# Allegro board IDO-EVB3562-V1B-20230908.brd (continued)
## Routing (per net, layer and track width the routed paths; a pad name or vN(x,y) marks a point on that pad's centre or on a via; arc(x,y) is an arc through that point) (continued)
N69867938: length 1.1
  TOP w0.254: R309.1 94.06,25.31 C219.2
N69867940: length 15
  TOP w0.254: v1(96.19,21.11) 96.43,21.35 96.43,24.36 R309.2 ; v1(94.65,21.11) 93.79,21.98 90.56,21.98 89.76,21.18 89.76,19.4 90.2,18.96 U25.10
  BOTTOM w0.254: v1(94.65,21.11) v1(96.19,21.11)
N69867965: length 5.2
  TOP w0.254: U25.8 96.2,20.23 95.61,20.81 95.61,21.57 96.04,22 96.04,23.34 C214.2
N69871260: length 2.1
  TOP w0.127: R454.2 R446.1 104.63,18 104.43,18 104.38,17.95 Q5.1
N69917404: length 3.6
  TOP w0.254: U14.4 17.37,10.84 17.13,10.6 16.46,10.6 C369.1 R138.1 R139.2
N69923813: length 3
  TOP w0.508: C114.2 67.92,71.22 J21.1
N69957333: length 4.4
  TOP w0.127: C147.2 49.18,69.57 J22.1
N69957443: length 26.8
  TOP w0.127: R189.1 53.16,68.64 52.69,68.64 52.43,68.89 52.43,69.52 52.72,69.81 54.51,69.81 55.3,70.6 55.3,72.96 52.66,75.6 50.47,75.6 46.87,79.19 46.87,82.02 50.09,85.24 J22.11
N69960536: length 20.5
  TOP w0.127: R193.1 38.13,69.82 36.35,71.6 36.35,75.24 40.42,79.3 40.42,84.8 J22.13
N69961030: length 3
  TOP w0.508: C163.2 24.98,70.59 24.8,70.77 J23.4
N69961588: length 5.6
  TOP w0.508: J23.5 23.53,70.14 23.85,69.81 C166.2
N69966336: length 22.7
  TOP w0.127: J23.12 18.76,85.83 20.48,84.11 21.39,84.11 31.6,73.9 31.6,72.53 R219.2
N70024964: length 1.2
  TOP w0.127: U29.3 94.02,68.68 R341.1
N70036634: length 1.5
  TOP w0.127: Q6.1 91.98,64.45 91.98,64.61 R456.2
N70058734: length 1.4
  TOP w0.254: R35.1 101.18,70.84 101.31,70.71 U6.3
N70074623: length 3.7
  TOP w0.254: U11.3 9.53,13.58 9.41,13.69 C265.2 8.8,14.01 9.55,14.76 R130.2
N70074833: length 3
  TOP w0.254: R373.2 C266.2 29.14,19.84 29.44,20.14 U12.3
N70075015: length 2.9
  TOP w0.254: R374.2 51.91,13.11 C267.2 51.84,12.56 52.17,12.56 U13.3
N70075198: length 2.5
  TOP w0.254: R375.2 16.1,14.78 C268.2 17.2,14 U14.3
N70088511: length 1.3
  TOP w0.203: R448.1 13.62,34.51 U59.12
N70100637: length 2.1
  TOP w0.127: U7.42 112.69,38.38 112.94,38.13 R414.1
N70130938: length 2.6
  BOTTOM w0.127: C339.2 29.82,57.06 30.9,57.06 31.4,57.56 U17.29
N70140073: length 1.1
  TOP w0.127: Q4.1 9.8,42.71 9.75,42.76 R453.2
N70164941: length 6.6
  TOP w0.254: R787.2 R1061.2 20.42,56.18 R1060.1 20.95,56.78 22.4,56.78 23.42,55.76 U70.9
N70165129: length 2.9
  TOP w0.254: R783.2 R782.2 23.27,54.64 23.51,54.41 U70.12
N70165139: length 7.5
  TOP w0.254: v1(23.62,57.06) 24.01,56.66 U70.7
  TOP w0.508: C810.1 21.05,53.06 v1(21.5,52.61)
  BOTTOM w0.508: v1(23.62,57.06) 21.5,54.94 v1(21.5,52.61)
N70165141: length 1.2
  TOP w0.508: C810.2 20.67,51.85 21.41,51.85
N70165164: length 1.1
  TOP w0.254: C815.2 20.42,54.7 20.35,54.77 R1061.1
N70166760: length 7.8
  TOP w0.254: Q8.1 21.84,41.25 22.28,41.69 C1012.1 R1063.1 22.7,40.55 20.61,40.55 19.97,41.18 R1062.2
N70166762: length 1.3
  TOP w0.254: Q7.3 17.56,42.12 16.98,41.54 R1062.1
N70166881: length 1.1
  TOP w0.254: Q7.1 18.06,44.94 R4.2
N70177512: length 2.8
  TOP w0.254: R1066.1 R1067.2 25.66,12.73 26.26,12.13 U71.4
N70177574: length 2.6
  TOP w0.254: U71.3 26.26,14.32 26.07,14.13 C1014.2 R1065.2
N70177973: length 2.3
  TOP w0.254: R1069.1 R1070.2 32.87,10.45 33.2,10.11 U72.4
N70178035: length 2.7
  TOP w0.254: U72.3 33.63,12.54 32.93,11.84 C1018.2 R1068.2
N70190247: length 5.3
  TOP w0.254: Q10.1 30.07,29.5 R1079.2 30.95,30.4 31.47,30.92 31.8,30.92 33,32.11 R1080.1 C1034.1
N70190249: length 6.1
  TOP w0.254: Q9.3 31.66,29.75 31.85,29.95 R1079.1 32.13,30.39 33.58,31.84 33.58,33.73 R1083.2
N70190329: length 2.8
  TOP w0.127: R1192.1 31.9,26.52 R1078.2
  TOP w0.254: Q9.1 31.16,27.2 31.78,26.57 R1078.2
N70208813: length 6.7
  TOP w0.508: C282.2 88.42,17.62 88.42,22.38 89.15,23.11 89.57,23.11
N70209347: length 2.8
  TOP w0.127: C1035.2 109.76,55.56 109.58,55.74 J10.22
N70209679: length 1.7
  TOP w0.381: C529.1 102.57,15.62 U42.1
N70209681: length 6.9
  TOP w0.381: C529.2 101.34,16.14 101.82,16.62 104.5,16.62 104.87,16.25 104.87,14.61 104.58,14.32 U42.3
N70209685: length 1.8
  TOP w0.254: U42.4 103.17,13.67 102.71,14.13 C527.1
N70209687: length 3.1
  TOP w0.254: U42.5 103.17,13.02 102.79,13.4 102.79,13.4 102.58,13.6 101.6,13.6 101.31,13.89 C527.2
N70209691: length 1.6
  TOP w0.381: C530.1 102.8,15.02 102.85,14.97 U42.2
N70209695: length 1.9
  TOP w0.381: C528.1 102.38,13.06 103.08,12.37 U42.6
N70210897: length 3.6
  TOP w0.254: R1169.2 R1170.1 C1039.1 105.04,23.02 104.35,23.7 U73.5
N70211090: length 2.4
  TOP w0.254: R1171.2 C1045.2 104.78,26.07 104.45,26.4 U73.1
N70266506: length 15.6
  TOP w0.127: R218.2 31.62,74.96 26.19,80.38 26.19,83.78 J23.10
N70266836: length 3.8
  TOP w0.127: v1(35.34,53.88) 34.77,53.32 R1200.1
  BOTTOM w0.127: v1(35.34,53.88) 34.82,54.4 U17.19
N70310222: length 5.8
  TOP w0.508: v1(127.67,16.29) v1(130.84,16.29)
  BOTTOM w0.508: C533.1 126.72,15.34 127,15.62 R461.2 v1(127.67,16.29) ; R462.2 v1(130.84,16.29)
N70310339: length 2.9
  TOP w0.508: U43.5 v1(130.72,11.08)
  BOTTOM w0.508: R460.1 C531.1 130.34,11.14 130.66,11.14 v1(130.72,11.08)
N70379039: length 2
  TOP w0.127: U18.13 121.49,31.04 R1211.2
N76747942: length 2.7
  BOTTOM w0.254: R209.1 32.32,60.77 U17.1
N76750177: length 2.5
  BOTTOM w0.254: U17.2 32.82,61.29 C341.2

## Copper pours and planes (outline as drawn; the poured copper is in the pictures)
GND on TOP (solid shape): 9.88,21 9.88,20.48 8.97,19.56 8.44,19.56 8.44,19.72 8.54,19.72 8.54,20.5 8.44,20.56 8.44,20.73 8.54,20.73 8.54,21.32 9.57,21.32
GND on TOP (solid shape): 40.3,13.26 40.37,13.36 40.48,13.34 41.55,12.26 41.55,11.59 40.93,11.59 40.93,11.49 40.77,11.49 40.77,12.39 40.3,12.39
GND on TOP (solid shape): 34.44,37.39 34.44,34.39 34.37,34.3 34.26,34.32 33.53,35.05 33.53,35.63 32.67,35.63 32.67,37.88 33.43,37.88 33.43,37.98 33.53,37.98 33.53,38.19 33.64,38.19
GND on TOP (solid shape): 94.49,47.23 94.6,47.25 94.66,47.16 94.66,42.79 94.3,42.42 93.72,42.42 93.72,42.21 92.84,42.21 92.74,42.27 92.77,42.38 94.27,43.88 94.27,47.01
GND on TOP (solid shape): 65.5,49.65 65.59,49.62 66.55,48.66 66.55,47.42 66.49,47.33 66.38,47.35 65.28,48.45 65.28,49.44 65.36,49.51 65.43,49.6
GND on TOP (solid shape): 105.95,41.74 105.95,41.16 106.05,41.16 106.05,41 105.96,41 105.95,41.01 105.8,41.08 105.63,41.1 105.33,41.1 105.1,41.23 104.84,41.25 104.76,41.27 104.72,41.35 104.72,41.78 105.91,41.78
GND on TOP (solid shape): 5.3,20.82 5.47,20.75 5.65,20.75 5.73,20.72 5.77,20.64 5.77,20.45 5.4,20.08 5.25,20.08 5.25,20.52 4.42,20.52 4.42,20.06 4.38,19.99 4.3,19.96 4.26,19.97 4.21,19.97 4.21,20.65 4.39,20.82
GND on TOP (solid shape): 86.07,40.65 86.16,40.59 86.14,40.48 85.79,40.13 84.35,40.13 83.67,39.45 83,39.45 82.94,39.54 82.87,39.61 82.83,39.69 82.87,39.77 82.96,39.86 83.03,39.97 83.03,39.98 83.36,40.3 83.73,40.3 84.07,40.65
GND on TOP (solid shape): 94.17,21.13 94.17,21.11 94.35,20.75 94.73,20.64 94.82,20.62 94.85,20.54 94.85,19.53 95.62,18.76 95.63,18.71 95.58,18.68 95.46,18.68 93.12,21.02 93.12,21.65 93.65,21.65
GND on TOP (solid shape): 57.14,51.13 57.14,50.6 57.13,50.56 57.1,50.55 57.05,50.54 56.99,50.53 54.63,50.53 54.63,50.53 54.49,50.55 54.36,50.53 54.3,50.53 54.22,50.46 53.76,50.46 53.66,50.53 53.68,50.64 54.22,51.17 57.1,51.17
GND on TOP (solid shape): 79.73,23.47 79.84,23.49 79.9,23.4 79.9,21.23 79.4,20.72 76.61,20.72 76.45,20.56 76.43,20.56 76.15,20.52 75.94,20.32 75.87,20.27 75.78,20.3 75.36,20.72 75.36,21.64 77,23.29 79.54,23.29
GND on TOP (solid shape): 91.85,8.2 91.94,8.14 91.92,8.03 90.94,7.05 90.71,7.27 86.16,7.27 85.65,6.76 85.61,6.79 85.49,6.86 85.35,6.89 85.34,6.89 84.73,7.5 84.3,7.5 84.14,7.59 83.97,7.62 83.89,7.65 83.86,7.72 83.86,8.2
GND on TOP (solid shape): 35.66,53.45 35.71,53.37 35.71,52.23 34.99,51.51 34.87,51.43 34.79,51.31 34.75,51.28 34.75,51.22 34.73,51.09 34.75,50.95 34.75,50.95 34.75,49.6 34.5,49.6 33.64,50.46 33.64,52.3 33.53,52.4 33.53,53.05 34.88,53.05 35.25,53.41 35.27,53.41 35.42,53.41 35.56,53.46
GND on TOP (solid shape): 19.6,22.46 19.67,22.49 19.74,22.46 19.96,22.33 20.21,22.34 20.3,22.32 20.34,22.24 20.34,19.73 20.32,19.72 19.92,19.72 19.92,19.89 20.1,20.07 20.1,21.14 19.65,21.59 18.98,21.59 18.88,21.65 18.91,21.76
GND on TOP (solid shape): 104.66,8.79 104.75,8.73 104.73,8.62 104.63,8.52 104.63,8.19 103.81,7.37 103.51,7.37 103.43,7.29 103.32,7.27 103.25,7.36 103.25,8.28 103.24,8.28 103.24,8.34 103.25,8.5 103.21,8.65 103.22,8.74 103.3,8.79
GND on TOP (solid shape): 9.77,17.79 9.77,17.64 9.73,17.56 9.64,17.55 9.13,17.42 9.04,16.91 9.03,16.82 8.95,16.77 8.5,16.77 8.48,16.75 8.42,16.78 8.42,18.06 8.45,18.1 9.46,18.1
GND on TOP (solid shape): 87.34,22.85 87.45,22.87 87.51,22.78 87.51,22.64 87.49,22.62 87.49,21.02 87.42,20.95 87.42,20.72 87.05,20.35 83.83,20.35 83.32,20.86 81.45,20.86 81.45,21.6 81.5,21.69 81.59,21.69 81.7,21.66 81.8,21.65 82.54,21.65 82.81,21.72 83,21.92 86.41,21.92
GND on TOP (solid shape): 113.3,34.14 113.41,34.16 113.47,34.07 113.47,32.9 113.82,32.54 113.95,32.54 113.95,31.78 113.9,31.78 113.78,31.67 113.76,31.67 113.76,31.66 112.91,31.66 112.53,32.04 111.18,32.04 111.08,32.1 111.11,32.21 111.34,32.44 111.34,33.74 111.16,33.92 111.14,34.03 111.23,34.09 113.25,34.09
GND on TOP (solid shape): 59.38,19.98 59.32,19.89 59.21,19.91 57.69,21.42 57.69,21.66 58.21,22.17 58.21,22.74 57.62,23.32 57.06,23.32 57.03,23.29 56.92,23.27 56.86,23.37 56.86,23.83 56.27,24.41 55.71,24.41 55.36,24.06 55.05,24.37 55.02,24.48 55.12,24.54 59.38,24.54
GND on TOP (solid shape): 90.48,30.02 90.53,29.93 90.53,26.57 90.47,26.54 90.46,26.55 88.27,26.55 87.92,26.2 87.92,25.92 87.38,25.92 87.37,25.91 87.31,25.93 87.31,26.55 87.21,26.6 87.21,26.78 87.31,26.78 87.31,27.54 87.21,27.54 87.21,27.64 86.81,27.64 86.71,27.7 86.74,27.81 87.01,28.09 88.15,28.09 89.98,29.92 90.01,29.91 90.2,29.92 90.37,30.01
GND on TOP (solid shape): 123.84,9.67 123.93,9.61 123.91,9.5 123.78,9.28 123.78,9.03 123.78,9.02 123.78,8.96 123.76,8.96 123.76,8.41 123.73,8.36 123.67,8.37 123.61,8.44 122.25,8.44 122.24,8.43 122.18,8.45 122.18,8.96 122.16,8.96 122.16,9.11 121.77,9.5 121.75,9.61 121.84,9.67
GND on TOP (solid shape): 23.44,11.31 23.55,11.33 23.62,11.24 24.1,11.24 24.58,10.76 25.98,10.76 26.37,10.36 26.37,9.69 25.68,9.69 25.65,9.65 25.59,9.64 25.56,9.69 24.78,9.69 24.72,9.59 24.54,9.59 24.54,9.69 23.78,9.69 23.78,9.59 23.68,9.59 23.68,9.46 23.55,9.32 23.43,9.29 23.37,9.39 23.37,10.49 23.16,10.49 23.16,10.66 23.37,10.66 23.37,11.24
GND on TOP (solid shape): 46.37,17.23 46.45,17.19 46.67,17.02 46.93,16.99 46.99,16.99 46.99,16.91 48.63,15.27 49.25,15.27 49.44,15.09 49.44,13.21 48.54,12.31 48.43,12.29 48.37,12.38 48.37,13.2 47.35,14.21 47.35,15.54 46.04,16.85 46.01,16.95 46.07,17.02 46.19,17.09 46.29,17.19
GND on TOP (solid shape): 92.16,13.18 92.16,11.86 89.74,11.86 89.43,12.03 89.08,11.95 88.6,12.13 88.23,11.77 88.22,11.73 86,11.73 85.95,11.76 85.96,11.82 86.01,11.87 86.01,12.88 86.37,13.24 89.67,13.24 89.79,13.36 91.98,13.36
GND on TOP (solid shape): 98.22,20.43 98.28,20.52 98.39,20.5 98.55,20.34 102.58,20.34 102.67,20.28 102.65,20.17 102.53,20.05 101.05,20.05 100.7,19.7 100.39,19.7 100.39,18.64 100.62,18.64 100.62,18.32 98.84,18.32 98.39,18.32 98.22,18.49 98.22,19.48 95.84,19.48 95.51,19.8 95.51,20.2 95.57,20.29 95.69,20.27 95.91,20.05 95.91,19.71 98.22,19.71
GND on TOP (solid shape): 94.1,24.98 94.1,24.83 95.49,24.83 95.76,24.56 95.78,24.45 95.68,24.39 95,24.39 95,24.29 94.9,24.29 94.9,23.53 95,23.53 95,23.43 95.49,23.43 95.71,23.21 95.71,22.99 94.1,22.99 94.1,22.84 93.93,22.84 93.93,22.99 92.54,22.99 92.27,23.26 92.25,23.37 92.34,23.43 93.03,23.43 93.03,23.53 93.12,23.53 93.12,24.29 93.03,24.29 93.03,24.39 92.54,24.39 92.27,24.65 92.25,24.76 92.34,24.83 93.93,24.83 93.93,24.98
GND on TOP (solid shape): 18.12,20.98 18.23,21 18.3,20.91 18.3,19.72 13.96,19.72 11.8,17.56 11.69,17.54 11.63,17.63 11.63,18.12 11.66,18.12 11.66,18.7 13.34,20.39 16.75,20.39 17.32,20.21 17.62,20.73 17.64,20.82 17.72,20.85 18,20.85
GND on TOP (solid shape): 29.43,8.65 29.54,8.67 29.6,8.58 29.6,7.39 29.6,7.38 29.7,6.93 30.14,6.78 30.22,6.76 30.26,6.68 30.26,3.16 31.01,2.4 31.04,2.29 30.94,2.23 25.25,2.23 22.97,4.51 22.97,5.85 23.91,5.85 24.06,5.7 25.21,5.7 25.36,5.85 25.89,5.85 28.6,8.55 29.34,8.55
GND on TOP (solid shape): 86.69,39.89 86.77,39.84 86.78,39.75 86.77,39.41 86.98,39.15 87.03,39.07 87.01,38.99 86.79,38.77 85.54,38.77 83.6,36.84 83.26,36.84 83.26,37.13 83.06,37.33 83.05,37.34 82.98,37.49 82.87,37.61 82.83,37.69 82.87,37.77 82.94,37.84 83,37.92 83.25,37.92 84.67,39.34 86.12,39.34 86.66,39.89
GND on TOP (solid shape): 84.23,43.61 85.86,43.61 85.87,43.56 85.93,43.37 86.07,43.23 86.11,43.15 86.08,43.07 85.96,42.92 85.92,42.74 85.88,42.67 85.81,42.64 84.18,42.64 83.57,43.26 83.07,43.26 83.06,43.3 82.99,43.47 82.87,43.61 82.83,43.69 82.87,43.77 82.99,43.9 83.06,44.07 83.07,44.09 83.24,44.26 83.58,44.26
GND on TOP (solid shape): 39.54,50.46 39.63,50.43 40.21,49.85 40.24,49.76 40.19,49.69 40.01,49.52 39.94,49.29 39.94,49.25 38.64,49.25 38.43,49.45 38.4,49.45 38.39,49.48 38.33,49.55 38.27,49.61 38.23,49.69 38.27,49.77 38.34,49.84 38.4,49.92 38.74,49.92 38.93,50.11 38.95,50.11 39.26,50.16 39.47,50.4
GND on TOP (solid shape): 100.86,15.48 101.63,15.48 101.63,14.61 100.83,14.61 100.83,13.65 101.09,13.65 101.47,13.27 101.63,13.27 101.63,12.69 100.88,12.69 100.88,12.15 99.04,12.15 98.39,11.5 98.28,11.48 98.22,11.57 98.22,11.86 95.91,11.86 95.91,11.79 94.61,11.79 94.01,11.19 93.9,11.17 93.84,11.26 93.84,12.8 94.46,13.42 95.91,13.42 95.91,13.36 98.22,13.36 98.22,14.14 98.7,14.14 98.82,14.26 100.14,14.26 100.39,14.51 100.39,15.68 99.96,16.11 99.31,16.11 99.22,16.17 99.24,16.28 99.43,16.48 100.86,16.48
GND on TOP (solid shape): 42.37,17.23 42.45,17.19 42.74,17 43.09,17.03 43.12,17.04 44.94,15.22 44.94,13.01 45.87,12.07 45.87,11.17 45.69,11.13 45.53,11.03 45.5,11.02 45.46,11.03 45.31,11.14 45.12,11.18 45.12,11.93 42.55,14.49 42.55,16.01 41.64,16.93 41.64,17.01 41.7,17.01 41.7,17.01 42.03,17.01 42.29,17.19
GND on TOP (solid shape): 130.02,44.83 130.13,44.86 130.2,44.76 130.2,44.2 130.15,44.2 129.73,43.68 130.23,43.24 130.25,43.24 130.96,42.54 130.96,42.44 130.89,42.44 130.88,42.45 130.51,42.54 130.19,42.34 128.46,42.34 127.58,43.22 127.56,43.33 127.66,43.39 128.58,43.39
GND on TOP (solid shape): 31.3,28.65 31.58,28.65 31.65,28.62 31.68,28.55 32.09,28.07 32.62,28.41 32.84,28.39 33.05,28.48 33.16,28.49 33.21,28.4 33.21,26.2 32.6,26.2 32.26,26.53 32.26,27 31.82,27 31.51,27.31 31.51,28.31 30.93,28.31 30.93,28.36 30.84,28.61 30.63,28.77 30.59,28.79 30.59,29.56 30.94,29.91 31.3,29.91
GND on TOP (solid shape): 31.67,7.55 33.8,7.55 34.18,7.93 34.73,7.93 34.73,7.55 34.95,7.32 35.35,7.32 35.35,5.85 35.87,5.85 35.94,5.77 36.43,5.77 36.51,5.85 38.06,5.85 38.06,7.3 38.35,7.3 38.35,5.85 39.06,5.85 39.06,7.32 39.35,7.32 39.35,5.85 40.44,5.85 40.44,4.24 38.43,2.23 37.02,2.23 36.92,2.29 36.95,2.4 37.53,2.99 37.53,4.2 37.53,4.21 37.07,4.82 36.61,4.21 36.61,4.2 36.61,3.36 36.11,2.87 31.85,2.87 31.17,3.54 31.17,7.77 31.19,7.83 31.19,7.89 31.2,7.94 31.29,7.94
GND on TOP (solid shape): 3.77,18.71 3.96,18.42 4.3,18.34 4.38,18.32 4.42,18.24 4.42,17.91 4.97,17.91 4.98,17.84 4.96,17.76 4.88,17.72 4.42,17.72 4.42,17.11 4.94,17.11 5.03,17.06 5.03,16.96 5.01,16.92 4.42,16.92 4.42,16.9 4.38,16.82 4.3,16.8 4.03,16.77 3.82,16.6 3.62,16.6 3.44,16.42 3.33,16.39 3.27,16.49 3.27,18.52 2.64,18.52 2.64,18.71 3.27,18.71 3.27,18.75 3.76,18.75
GND on TOP (solid shape): 92.12,19.23 92.18,19.32 92.29,19.3 94.75,16.85 95.91,16.85 95.91,16.68 92.12,16.68 92.12,16.94 89.81,16.94 89.81,16.04 89.74,16.04 89.73,16.02 89.13,16.02 88.57,15.46 85.97,15.46 84.36,13.85 84.36,13.21 84.3,13.12 84.19,13.14 84.12,13.21 84.14,13.24 84.16,13.77 83.68,13.99 83.66,13.99 81.14,16.51 81.14,17.05 81.33,17.25 81.4,17.52 81.4,17.62 81.44,17.67 81.49,17.66 82.6,16.54 88.53,16.54 88.63,16.64 88.7,16.64 88.7,16.71 89.67,17.68 89.67,18.9 89.7,18.95 89.76,18.94 89.81,18.88 89.81,18.44 92.12,18.44
GND on TOP (solid shape): 78.31,50.23 78.42,50.25 78.48,50.16 78.48,50.03 77.78,49.33 77.78,48.16 77.61,47.58 78.14,47.29 78.22,47.27 78.26,47.19 78.26,47.14 77.97,46.84 77.94,46.84 77.57,46.74 77.4,46.41 77.33,46.32 77.22,46.34 76.75,46.81 76.76,46.84 76.6,47.26 76.16,47.37 76.07,47.39 76.03,47.47 76.03,47.95
GND on TOP (solid shape): 85.38,3.59 85.48,3.53 85.45,3.41 85.96,2.17 86.47,3.41 86.45,3.53 86.54,3.59 87.18,3.59 88.73,2.04 88.75,1.93 88.65,1.87 85.37,1.87 84.77,2.47 84.77,2.9 84.72,3.18 84.57,3.42 84.56,3.53 84.65,3.59
GND on TOP (solid shape): 94.14,31.53 94.19,31.53 94.19,31.4 94.14,31.4 94.14,30.64 94.15,30.64 94.18,30.58 94.13,30.53 94.11,30.53 94.11,30.51 93.89,30.29 93.89,28.05 94.29,27.64 95.23,27.64 95.32,27.59 95.32,27.49 95.51,26.51 96.51,26.45 96.61,26.45 96.67,26.36 96.67,24.83 96.6,24.74 96.49,24.76 95.96,25.29 95.96,25.78 94.1,25.78 94.1,25.64 93.93,25.64 93.93,25.78 92.31,25.78 92.31,30.03 92.31,30.03 92.31,30.35 92.43,30.87 91.99,31.17 91.97,31.17 91.6,31.55 91.78,31.73 93.09,31.73 93.51,32.15 94.14,32.15
GND on TOP (solid shape): outline of 116 points within 5.9,22.84 16.57,26.45
GND on TOP (solid shape): 88.97,31.96 89.07,31.94 89.99,31.02 90.02,30.92 89.95,30.85 89.68,30.65 89.6,30.32 89.61,30.29 87.93,28.62 86.79,28.62 85.92,27.75 85.92,23.21 85.84,23.12 84.15,23.12 83.07,24.19 83.07,24.21 83.01,24.43 82.87,24.61 82.83,24.69 83.07,25.19 82.83,25.69 82.87,25.77 83.07,26.15 82.92,26.56 82.9,26.67 83,26.73 83.26,26.73 84.87,28.34 84.87,29.49 86.84,31.45 88.28,31.45 88.29,31.45 88.7,31.52 88.9,31.87
GND on TOP (solid shape): 7.64,41.96 7.47,41.76 7.43,41.49 7.44,41.47 7.33,41.36 7.33,41.02 6.22,41.02 6.22,40 3.83,37.61 3.83,34.8 3.13,34.09 2.7,34.09 2.48,34.06 2.27,33.97 2.17,33.97 2.11,34.05 2.11,34.62 2.17,34.71 2.27,34.7 3.43,35.29 2.27,35.88 2.17,35.87 2.11,35.96 2.11,36.56 3.43,36.56 3.43,38.02 2.11,38.02 2.11,41.84 2.66,42.39 5.1,42.39 5.56,42.34 5.84,42.71 5.85,42.75 7.4,42.75 7.4,43.34 7.64,43.34
GND on TOP (solid shape): 17.15,23.07 17.15,22.53 17.14,22.5 17.1,22.48 16.69,21.81 17.46,21.66 17.53,21.69 17.6,21.66 17.7,21.58 17.82,21.54 17.83,21.54 17.88,21.49 17.77,21.39 11.74,21.39 9.43,19.08 9.38,19.07 9.34,19.11 9.34,19.18 10.42,20.26 10.42,21.23 9.79,21.85 6.74,21.85 6.2,21.31 6.1,21.28 6.03,21.35 5.73,21.67 5.3,21.61 4.06,21.61 3.42,20.97 3.42,20.36 3.18,20.12 2.85,20.12 2.64,20.12 2.64,22.3 3.36,23.02 6.13,23.02 7.07,22.08 11.64,22.08 15.12,22.81 15.68,22.81 15.68,22.77 16.35,22.35 16.51,23.12 16.48,23.2 16.51,23.27 16.58,23.37 16.63,23.48 16.63,23.5 16.68,23.54
GND on TOP (solid shape): 78.37,17.23 78.87,16.98 79.37,17.23 79.87,16.98 80.37,17.23 80.45,17.19 80.52,17.11 80.6,17.05 80.6,16.29 81.57,15.32 81.6,15.21 81.5,15.15 79.68,15.15 79.15,14.62 79.15,13.52 79.43,13.24 80.7,13.24 80.93,13.01 80.93,11.81 80.95,11.79 80.93,11.73 76.22,11.73 76.07,11.88 76.07,11.9 75.83,12.39 75.28,12.33 75.22,12.31 75.15,12.33 75.14,12.34 75.11,12.42 75.14,12.49 75.3,12.74 75.28,13.03 75.3,13.12 75.38,13.16 77.18,13.16 78.07,14.05 78.07,15.61 77.83,15.84 77.83,16.53 77.84,16.54 77.85,16.69 77.82,16.85 77.83,16.94 77.91,16.98 78.12,17.05 78.29,17.19
GND on TOP (solid shape): 118.41,11.58 118.44,11.48 118.37,11.41 118.14,11.24 118.05,10.97 118.03,10.94 118,10.92 117.94,10.92 117.9,10.93 117.88,10.95 117.53,11.27 117.08,11.14 117,11.1 116.93,11.14 116.27,11.2 116.18,10.55 116.2,10.48 116.17,10.42 116.14,10.39 116.11,10.36 116.08,10.34 116.05,10.34 115.41,10.17 115.55,9.53 115.55,8.99 115.42,8.99 115.42,7.08 115.55,7.08 115.55,5.73 115.62,5.66 115.64,5.53 115.52,5.49 115.25,5.53 114.98,5.5 114.89,5.52 114.85,5.6 114.85,7.11 114.94,7.11 114.94,7.69 115.19,7.94 115.19,9.66 115.19,9.67 115.19,9.69 115.14,9.99 114.92,10.19 114.9,10.22 114.9,10.26 114.92,10.58 114.73,10.84 114.73,11.49 115.9,11.49 115.9,11.89 116.09,12.09 117.91,12.09
GND on TOP (solid shape): outline of 108 points within 74.59,4.33 82.97,10.94
GND on BOTTOM (solid shape): 56.19,55.51 52.59,55.51 52.59,59.11 56.19,59.11
GND on BOTTOM (solid shape): 61.37,49.36 61.05,49.03 60.94,49.01 60.88,49.11 60.88,51.98 61.37,51.98
GND on BOTTOM (solid shape): 56.15,50.6 56.4,50.35 56.4,49.83 56.32,49.75 55.79,49.75 55.79,50.45 55.69,50.45 55.69,50.55 55.48,50.55 55.48,50.76 55.29,50.94 55.29,51.17 55.5,51.17 55.5,51.98 56.15,51.98
GND on BOTTOM (solid shape): 74.48,51.16 74.48,49.97 74.09,49.57 73.69,49.57 73.69,51.32 73.64,51.37 73.63,51.43 73.67,51.46 73.77,51.46 73.98,51.67
GND on BOTTOM (solid shape): 77.28,52.27 76.63,51.62 76.52,51.6 76.46,51.7 76.46,51.89 76.25,51.89 76.25,52.04 76.73,52.53 76.73,53.31 76.8,53.37 77.28,53.37
GND on BOTTOM (solid shape): 113.47,58.62 113.47,56.68 113.39,56.61 113.32,56.52 113.25,56.47 113.16,56.49 112.82,56.83 112.82,58.71 113.39,58.71
GND on BOTTOM (solid shape): 69.28,56.14 69.37,56.14 69.37,56.04 70.21,56.04 70.21,55.73 70,55.52 68.79,55.52 68.12,54.84 65.7,54.84 65.63,54.92 65.62,54.97 65.66,55 66.99,55 66.99,56.28 67.37,56.66 69.28,56.66
GND on BOTTOM (solid shape): 20.27,46.53 20.34,46.62 20.45,46.6 22.44,44.61 22.46,44.5 22.37,44.44 22.03,44.44 20.27,46.2
GND on BOTTOM (solid shape): 71.12,5.32 71.22,5.25 71.19,5.14 70.84,4.79 67.95,4.79 67.86,4.85 67.88,4.96 68.24,5.32
GND on BOTTOM (solid shape): 85.64,19.87 85.66,19.76 85.57,19.69 85.09,19.69 82.95,21.84 82.93,21.95 83.02,22.01 83.5,22.01
GND on BOTTOM (solid shape): 101.11,12.22 101.14,12.11 101.04,12.04 98.7,12.04 98.34,12.4 98.32,12.51 98.41,12.57 100.76,12.57
GND on BOTTOM (solid shape): 112.41,35.96 112.51,35.9 112.48,35.79 112.11,35.42 107.72,35.42 107.63,35.48 107.65,35.59 108.02,35.96
GND on BOTTOM (solid shape): 58.9,21.39 59,21.33 58.97,21.22 56.85,19.09 43.05,19.09 42.95,19.15 42.97,19.26 43.2,19.49 43.2,21.39
GND on BOTTOM (solid shape): 83.8,10.03 83.86,10.12 83.98,10.1 86.1,7.97 86.12,7.86 86.03,7.8 84.94,7.8 84.75,7.6 83.8,8.55
GND on BOTTOM (solid shape): 31.58,25.65 31.86,25.37 31.87,25.31 31.83,25.28 31.8,25.28 31.12,24.6 30.68,24.6 30.59,24.66 30.61,24.77 31.46,25.63 31.46,26.82 31.58,26.82
GND on BOTTOM (solid shape): 49.08,56.77 49.18,56.77 49.18,56.67 49.94,56.67 49.94,56.69 50.01,56.72 50.44,56.29 50.44,56 50.16,55.72 50.06,55.69 49.99,55.76 48.13,55.76 48.13,55.54 47.78,55.54 47.56,55.76 47.31,55.76 47.31,57.04 47.56,57.3 49.08,57.3
GND on BOTTOM (solid shape): 111.26,15.44 111.26,15.3 113.14,13.42 113.16,13.31 113.07,13.25 112.11,13.25 110.18,15.17 110.16,15.28 110.26,15.34 110.77,15.34 110.98,15.56 111.15,15.56
GND on BOTTOM (solid shape): 115.6,17.5 115.6,16.92 115.69,16.92 115.69,16.85 115.67,16.84 115.56,16.65 115.54,16.43 115.54,16.41 115.46,16.33 115.1,16.33 113.72,17.71 111.86,17.71 111.78,17.8 111.77,17.85 111.82,17.88 115.23,17.88
GND on BOTTOM (solid shape): 117.75,11.42 117.75,11.34 117.7,11.26 117.61,11.25 117.49,11.28 117.36,11.28 117.33,11.28 117.03,11.59 117.03,11.94 116.47,12.5 116.46,12.55 116.51,12.58 116.59,12.58
GND on BOTTOM (solid shape): 54.55,51.17 54.76,51.17 54.76,50.72 54.78,50.63 54.73,50.56 54.73,50.52 54.67,50.52 54.66,50.52 54.51,50.55 54.36,50.53 54.35,50.53 54.3,50.53 54.3,50.72 53.81,50.72 53.81,51.98 54.39,51.98 54.39,52.07 54.55,52.07
GND on BOTTOM (solid shape): 117.38,45.65 117.38,40.95 117.48,40.85 117.51,40.74 117.41,40.67 110.12,40.67 107.25,43.55 107.22,43.66 107.32,43.72 107.83,43.72 109.25,45.14 109.25,46.66 109.61,47.02 116.01,47.02
GND on BOTTOM (solid shape): 37.03,55.5 37.06,55.55 37.11,55.54 37.9,54.76 38.22,54.76 38.22,54.55 39.12,54.55 39.12,54.39 39.02,54.39 39.02,53.63 39.12,53.63 39.12,53.53 39.33,53.53 39.33,52.42 38.32,51.4 38.21,51.38 38.15,51.48 38.15,54.26 37.03,55.38
GND on BOTTOM (solid shape): 49.55,60.08 49.66,60.1 49.73,60.01 49.73,59.57 50.36,58.93 50.36,58.62 50.54,58.44 50.58,58.38 50.58,58.32 50.54,58.3 50.04,58.3 50.04,58.86 49.94,58.86 49.94,58.96 49.36,58.96 49.11,59.22 49.11,59.87 49.34,59.87
GND on BOTTOM (solid shape): 88.62,27.83 88.65,27.75 88.61,27.68 88.5,27.61 88.26,27.61 88.16,27.83 88.18,27.98 84.5,31.66 84.47,31.77 84.57,31.83 84.62,31.83
GND on BOTTOM (solid shape): 31.71,32.44 31.73,32.33 31.64,32.27 31.41,32.27 29.92,30.78 29.81,30.76 29.75,30.85 29.75,31.25 29.35,31.66 27.44,31.66 27.41,31.69 27.33,31.69 27.24,31.78 27.22,31.82 27.23,31.85 27.33,32.03 27.35,32.23 27.34,32.26 27.8,32.71 31.44,32.71
GND on BOTTOM (solid shape): 6.64,49.56 6.74,49.56 6.74,49.47 6.95,49.47 6.95,49.35 6.79,49.35 6.79,47.49 7.01,47.49 7.1,47.43 7.08,47.32 6.89,47.13 6.89,45.79 5.7,45.79 5.54,45.95 5.52,46.02 5.52,46.18 5.6,46.29 5.62,46.43 5.62,47.38 5.11,47.89 5.11,48.42 5.75,48.42 5.75,48.44 5.82,48.52 5.85,48.52 5.85,48.54 6,48.7 6,50.41 6.64,50.41
GND on BOTTOM (solid shape): 32.98,8.63 33.16,8.81 33.4,8.71 33.47,8.59 33.84,8.59 33.86,8.57 34.34,8.57 34.93,7.98 34.95,7.87 34.85,7.81 32.33,7.81 32.23,7.71 31.41,7.71 31.32,7.77 31.34,7.88 31.57,8.11 32.55,8.11 32.97,8.53
GND on BOTTOM (solid shape): 125.88,25.45 126.26,25.07 126.26,24.4 126.16,24.3 125.57,24.3 125.48,24.37 125.5,24.48 125.73,24.71 125.73,25.84 125.31,26.26 125.31,30.3 125.55,30.53 125.55,31.14 125.22,31.47 125.25,31.5 125.34,31.87 125.14,32.18 125.1,32.26 125.13,32.34 125.46,32.67 125.88,32.67
GND on BOTTOM (solid shape): 118.08,20.04 118.19,20.07 118.26,19.97 118.26,17.03 117.97,16.74 117.88,16.71 117.8,16.77 117.6,16.97 117.31,17.02 117.29,17.01 116.73,17.57 116.66,17.57 116.66,17.78 116.08,17.78 115.9,17.96 115.88,18.07 115.97,18.14 116.18,18.14
GND on BOTTOM (solid shape): 122.73,10.96 122.77,10.89 122.77,10.08 123.55,9.29 122.56,8.3 120.81,8.3 120.72,8.36 120.74,8.47 121.22,8.95 121.23,8.95 121.64,9.26 121.54,9.76 121.52,9.78 121.52,9.93 122.58,10.98 122.65,10.99
GND on BOTTOM (solid shape): 112.32,16.04 112.72,15.69 113.2,15.92 113.27,15.97 113.35,15.94 113.65,15.64 113.65,15.2 114.67,14.18 114.69,14.07 114.6,14.01 113.69,14.01 112.05,15.65 112.05,15.77 111.91,15.91 111.89,16.02 111.98,16.08 112.31,16.08
GND on BOTTOM (solid shape): 34.73,51.3 34.75,51.3 34.75,51.23 34.75,51.22 35.21,50.61 35.67,51.22 35.67,51.23 35.67,51.3 36.17,51.3 36.17,50.22 36.11,50.12 36,50.15 35.78,50.36 34.13,50.36 33.83,50.67 33.83,52.1 34.58,52.1 34.58,52.2 34.73,52.2
GND on BOTTOM (solid shape): 23.19,22.64 23.53,22.64 23.62,22.58 23.6,22.47 23.19,22.05 22.81,22.05 22.73,22.1 22.72,22.2 22.55,22.78 21.95,22.73 21.88,22.7 21.81,22.73 21.79,22.75 21.79,22.82 21.85,22.82 22.31,23.27 22.56,23.27
GND on BOTTOM (solid shape): 30.71,55.28 30.82,55.3 30.88,55.21 30.88,54.98 31.16,54.69 31.38,54.69 31.41,54.65 31.44,54.62 31.31,54.24 31.52,53.89 31.52,53.48 31.26,53.23 31.26,53.16 31.05,53.16 31.05,51.66 30.99,51.56 30.88,51.59 29.84,52.62 29.23,52.62 29.02,52.83 29.02,52.99 29.12,52.99 29.12,53.75 29.02,53.75 29.02,53.91 29.92,53.91 29.92,54.49
GND on BOTTOM (solid shape): 47.56,55.01 48.13,55.01 48.13,54.8 49.03,54.8 49.03,54.64 48.93,54.64 48.93,53.88 49.03,53.88 49.03,53.78 49.47,53.78 49.51,53.75 49.5,53.7 49.44,53.63 49.44,52.87 48.67,52.87 48.67,52.94 48.47,53.14 47.63,53.14 47.54,53.05 47.44,53.05 47.44,52.95 47.38,52.89 47.38,52.54 47.37,52.5 47.31,52.4 47.21,52.34 47.14,52.32 46.92,52.1 46.03,52.1 45.92,52.1 45.87,52.19 45.87,53.53 46.16,53.53 46.16,53.63 46.26,53.63 46.26,54.39 46.16,54.39 46.16,54.64 46.26,54.64 46.26,55.22 46.27,55.23 47.34,55.23
GND on BOTTOM (solid shape): 85.17,11.6 85.2,11.65 85.26,11.64 87.48,9.42 90.77,9.42 91.21,9.86 96.5,9.86 96.79,9.57 96.81,9.47 96.73,9.4 96.49,9.3 96.34,9.09 96.33,9.05 96.29,9.05 96.21,9.09 96.19,9.17 95.9,9.69 95.32,9.53 93.79,9.53 93.47,9.53 93.01,9.07 87.61,9.07 85.17,11.51
GND on BOTTOM (solid shape): 60.98,18.84 61.09,18.55 61.36,18.39 61.37,18.39 63.44,16.33 63.44,16.31 63.46,16.17 63.52,16.04 63.53,15.94 63.44,15.88 59.46,15.88 59.37,15.93 59.36,16.02 59.26,16.51 58.78,16.64 58.77,16.63 58.1,16.63 57.46,15.99 57.38,15.99 57.33,16.02 57.34,16.08 60.16,18.89 60.98,18.89
GND on BOTTOM (solid shape): 21,22.82 21.09,22.76 21.08,22.66 21.04,22.18 21.45,21.91 21.48,21.89 21.5,21.86 21.5,21.79 21.8,21.49 21.82,21.38 21.73,21.32 20.5,21.32 19.76,22.07 19.76,22.26 19.8,22.35 19.9,22.36 20.34,22.39 20.56,22.77 20.56,22.82
GND on BOTTOM (solid shape): 129.62,43.52 129.71,43.55 129.79,43.5 130.07,43.26 130.44,43.3 130.54,43.3 130.59,43.21 130.59,42.55 130.54,42.55 130.34,42.48 130.19,42.34 129.84,42.34 128.44,40.93 128.34,40.91 128.27,40.99 128.11,41.29 127.78,41.41 127.71,41.43 127.68,41.51 127.68,41.58
GND on BOTTOM (solid shape): 9.18,43.13 9.24,43.22 9.35,43.2 9.47,43.08 9.47,40.17 9.41,40.08 9.3,40.1 8.93,40.46 8.97,40.5 9.03,41.07 8.49,41.29 8.39,41.31 8.36,41.41 8.36,41.71 8.19,41.95 8.14,42.02 8.17,42.1 9.18,43.11
GND on BOTTOM (solid shape): 84.77,6.15 84.85,6.18 84.92,6.14 84.97,6.08 85.03,6.02 85.08,5.95 85.05,5.87 84.02,4.84 74.09,4.84 74.04,4.94 73.97,5.03 73.95,5.14 74.04,5.2 75.27,5.2 75.73,5.66 76.29,5.66 76.36,5.63 76.39,5.55 76.58,5.17 77,5.09 77.01,5.09 79.05,5.09 79.05,5.09 79.48,5.17 79.67,5.55 79.7,5.63 79.77,5.66 83.16,5.66 83.31,5.81 84.42,5.81
GND on BOTTOM (solid shape): 63.32,60.44 63.37,60.37 63.46,60.14 63.66,59.99 63.72,59.91 63.7,59.82 62.02,58.15 61.97,58.15 61.96,58.16 61.87,58.23 61.76,58.28 61.73,58.29 61.73,58.84 61.76,58.92 61.85,58.94 62.37,59.19 62.28,59.76 62.24,59.8 62.32,59.88 62.35,59.86 62.81,59.9 63.02,60.31 63.05,60.38 63.11,60.42 63.17,60.43 63.23,60.45
GND on BOTTOM (solid shape): 65.41,19.2 65.4,19.19 65.39,18.84 65.61,18.58 65.62,18.57 68.13,16.06 68.16,15.95 68.06,15.88 64.39,15.88 64.3,15.94 64.31,16.04 64.38,16.42 64.15,16.73 64.14,16.74 62.33,18.54 62.31,18.64 62.37,18.71 62.47,18.77 62.55,18.84 62.64,18.88 62.72,18.83 63.04,18.61 63.42,18.71 63.46,18.72 63.49,18.7 63.83,18.51 64.19,18.63 64.77,18.53 65.01,19.06 65.17,19.13 65.29,19.24 65.3,19.26 65.41,19.26
GND on BOTTOM (solid shape): 69.79,27.33 69.86,27.33 69.91,27.3 69.9,27.25 69.77,27.12 69.75,27.12 69.3,26.95 69.24,26.47 69.23,26.38 69.14,26.33 68.86,26.33 68.85,26.32 68.82,26.32 68.28,25.8 68.92,25.4 68.96,25.4 68.99,25.38 69.03,25.3 68.96,25.24 68.93,25.24 68.4,24.87 68.73,24.31 68.8,24.24 68.78,24.14 68.67,23.92 68.69,23.68 68.67,23.58 68.59,23.54 65.92,23.54 65.44,24.02 65.45,24.04 65.39,24.34 65.17,24.55 65.12,24.62 65.14,24.71 67.91,27.48 69.64,27.48
GND on BOTTOM (solid shape): 93.14,33.98 93.25,34.01 93.32,33.91 93.32,32.46 93.12,32.27 93.12,31.72 93.16,31.66 93.19,31.55 93.16,31.44 93.12,31.37 93.12,31.04 93.16,30.98 93.19,30.87 93.16,30.76 93.12,30.69 93.12,30.41 93.32,30.22 93.32,29.03 93,28.71 93,28.69 92.93,28.66 92.31,29.28 92.31,30.35 92,31.17 91.64,30.36 91.65,30.35 91.65,30.22 91.59,30.22 91.51,30.23 91.43,30.24 91.34,30.27 91.32,30.37 91.06,30.94 90.46,30.76 90.43,30.74 90.39,30.75 90.34,30.78 90.34,30.95 92.27,32.88 92.29,32.88 92.78,33.11 92.73,33.65 92.72,33.76 92.81,33.81 92.98,33.81
GND on BOTTOM (solid shape): 70.48,18.36 75.82,18.36 76.75,19.29 76.86,19.31 76.92,19.21 76.92,16.81 76.92,16.8 77.1,16.28 77.65,16.28 79.59,16.28 79.77,16.1 79.79,15.99 79.7,15.93 77.16,15.93 76,14.76 76.11,14.66 76.11,14.49 76.05,14.4 75.94,14.42 74.59,15.76 74.59,16.31 74.74,16.45 74.77,16.45 75.28,17.1 74.47,17.23 74.39,17.19 74.31,17.23 73.59,17.24 73.68,16.53 73.68,15.91 73.62,15.81 73.51,15.84 71.9,17.44 69.87,17.44 68.07,19.24 68.07,19.27 67.94,19.68 67.53,19.81 67.5,19.81 67.12,20.19 66.42,20.19 65.93,20.67 65.91,20.79 66,20.85 67.99,20.85
GND on BOTTOM (solid shape): 16.07,44.04 16.1,43.96 16.05,43.88 15.81,43.48 16.02,43.07 16.02,42.7 16.79,41.93 17.58,41.93 19.72,39.79 19.73,39.67 19.61,39.62 16.39,38.11 17.64,34.77 17.7,34.66 17.6,34.58 16.69,34.58 16.14,34.02 16.14,33.1 17.68,31.55 21.37,31.55 21.76,31.16 21.78,31.05 21.68,30.99 17.78,30.99 16.97,30.19 16.95,30.19 16.85,30.19 16.75,30.18 16.67,30.19 16.63,30.25 16.17,30.61 15.7,30.26 15.66,30.21 15.59,30.19 15.37,30.17 15.19,30.06 14.4,29.87 14.92,29.24 14.94,29.25 15.26,28.93 15.28,28.82 15.19,28.76 13.19,28.76 12.11,29.84 12.08,29.92 12.12,30 12.28,30.2 12.32,30.45 12.31,30.48 13.3,31.46 13.3,37.54 10.76,40.07 10.76,44.03 10.54,44.26 10.54,44.31 10.59,44.36 10.72,44.23 15,44.23 15.44,44.67
GND on BOTTOM: 75.85,63.53 75.8,63.58 75.8,64.35 75.66,64.49 75.66,65.96 75.65,65.96 75.65,66.78 76.07,67.2 76.65,67.2 76.82,67.04 76.82,66.78 76.39,66.35 76.39,66.1 76.31,66.03 76.31,64.44 76.39,64.36 76.39,63.58 76.33,63.53
GND on L2-VCC: 0.51,87.97 0.95,89.05 2.03,89.49 118.47,89.49 118.65,89.31 118.65,88.55 118.78,88.42 122.97,88.42 123.1,88.55 123.1,89.31 123.27,89.49 132.97,89.49 134.05,89.05 134.49,87.97 134.49,2.03 134.05,0.95 132.97,0.51 2.03,0.51 0.95,0.95 0.51,2.03 ; 5 cut-outs
GND on L3-GND: 2.03,0.51 0.95,0.95 0.51,2.03 0.51,87.97 0.95,89.05 2.03,89.49 13.75,89.49 13.75,77.29 15.32,75.72 17.69,75.72 18.7,76.74 18.7,78.77 16.92,80.55 16.92,86.56 17.13,86.77 31.32,86.77 31.53,86.56 31.53,80.8 29.75,79.03 29.75,76.87 31.02,75.6 36.31,75.6 37.75,77.04 37.75,78.6 35.85,80.51 35.85,85.93 36.69,86.77 50.62,86.77 50.96,86.44 50.96,81.02 49.05,79.11 49.05,76.78 50.24,75.6 56.12,75.6 57.69,77.17 57.69,78.73 55.53,80.89 55.53,86.18 55.87,86.52 70.18,86.52 70.39,86.31 70.39,80.76 68.49,78.86 68.49,76.91 69.67,75.72 72.13,75.72 73.44,77.04 73.44,89.49 118.47,89.49 118.65,89.31 118.65,88.55 118.78,88.42 122.97,88.42 123.1,88.55 123.1,89.31 123.27,89.49 132.97,89.49 134.05,89.05 134.49,87.97 134.49,2.03 134.05,0.95 132.97,0.51
GND_EARTH on TOP: 32.54,87.03 31.78,87.79 16.67,87.79 15.91,87.03 15.91,80.04 17.69,78.26 17.69,77.2 17.23,76.75 15.77,76.75 14.76,77.76 14.76,89.49 72.42,89.49 72.42,77.5 71.66,76.74 70.14,76.74 69.5,77.38 69.5,78.52 71.41,80.42 71.41,86.77 70.64,87.54 55.4,87.54 54.52,86.65 54.52,80.42 56.67,78.26 56.67,77.63 55.66,76.61 50.71,76.61 50.07,77.25 50.07,78.65 51.98,80.55 51.98,86.9 51.09,87.79 36.23,87.79 34.83,86.39 34.83,80.17 36.74,78.26 36.74,77.5 35.85,76.61 31.5,76.61 30.77,77.35 30.77,78.57 32.54,80.35
GND_EARTH on BOTTOM: 2.95,78.77 13.57,78.77 14.76,79.97 14.76,89.49 72.42,89.49 72.42,77.5 71.51,76.59 70.29,76.59 69.5,77.38 69.5,78.52 71.41,80.42 71.41,86.77 70.64,87.54 55.4,87.54 54.52,86.65 54.52,80.42 56.67,78.26 56.67,77.63 55.66,76.61 50.71,76.61 50.07,77.25 50.07,78.65 51.98,80.55 51.98,86.9 51.26,87.61 36.05,87.61 34.83,86.39 34.83,80.75 36.94,78.65 36.94,77.3 36.15,76.51 31.35,76.51 30.61,77.25 30.61,78.42 32.54,80.35 32.54,87.03 31.96,87.61 16.49,87.61 15.91,87.03 15.91,80.09 17.69,78.32 17.69,77.2 17.25,76.77 9.84,76.77 9.18,76.11 9.18,73.52 7.08,71.41 3.24,71.41 1.75,72.91 1.75,77.57
GND_EARTH on L2-VCC: 72.45,77.48 71.69,76.72 70.29,76.72 69.53,77.48 69.53,78.49 71.43,80.4 71.43,86.75 70.67,87.51 55.43,87.51 54.54,86.62 54.54,80.4 56.57,78.37 56.57,77.48 55.68,76.59 50.73,76.59 50.1,77.22 50.1,78.62 52,80.53 52,86.88 51.11,87.76 36.25,87.76 34.86,86.37 34.86,80.35 36.96,78.24 36.96,77.25 36.3,76.59 31.5,76.59 30.77,77.33 30.77,78.57 32.57,80.37 32.57,87 31.81,87.76 16.7,87.76 15.93,87 15.93,80.07 17.69,78.32 17.69,77.2 17.2,76.72 15.81,76.72 14.79,77.73 14.79,89.47 72.45,89.47
GND_EARTH on L3-GND: 32.54,86.98 31.74,87.79 16.71,87.79 15.91,86.98 15.91,80.04 17.69,78.26 17.69,77.25 17.18,76.74 15.74,76.74 14.76,77.71 14.76,89.49 72.42,89.49 72.42,77.46 71.7,76.74 70.09,76.74 69.5,77.33 69.5,78.44 71.41,80.34 71.41,86.73 70.6,87.54 55.45,87.54 54.52,86.6 54.52,80.47 56.67,78.31 56.67,77.59 55.7,76.61 50.66,76.61 50.07,77.21 50.07,78.69 51.98,80.59 51.98,86.86 51.04,87.79 36.27,87.79 34.83,86.35 34.83,80.09 36.74,78.18 36.74,77.46 35.89,76.61 31.53,76.61 30.77,77.38 30.77,78.52 32.54,80.3
VBAT_WL_1T1R on TOP: 126.25,25.48 125.92,25.81 125.13,25.81 124.95,25.64 124.39,25.64 124.39,25.65 122.98,25.65 122.97,25.66 122.97,26.42 123.07,26.53 126.12,26.53 126.25,26.65 127.5,26.65 127.5,25.5 127.44,25.43 127.31,25.43 127.31,24.29 127.21,24.19 126.45,24.19 126.25,24.39
VCC1V2_DVP on BOTTOM: 16.67,8.21 13.55,11.34 13.55,12.52 10.14,15.92 10.14,17.81 9.68,18.27 8.24,18.27 7.07,19.44 7.07,19.77 7.27,19.97 8.16,19.97 8.17,19.96 8.33,19.96 9,19.29 10.4,19.29 11.22,18.46 11.22,17.06 14.76,13.52 14.76,12.68 14.73,12.48 14.76,12.3 14.76,12.29 14.76,11.84 17.05,9.56 20.07,9.56 20.33,9.3 20.33,8.52 20.02,8.21
VCC1V8_DVP on TOP: 31.02,16.16 31.02,17.18 31.02,18.52 31.12,18.63 31.88,18.63 32.09,18.42 32.09,17.97 32.32,17.74 33.31,17.74 33.51,17.53 33.51,16.11 33.18,15.78 31.4,15.78
VCC1V8_DVP on BOTTOM: 5.87,19.06 5.87,20.43 6.43,20.99 7.09,20.99 7.42,20.66 7.42,20.43 6.89,19.9 6.89,19.31 8.24,17.97 8.85,17.97 9.93,16.89 9.93,15.72 12.63,13.01 12.63,11.89 16.49,8.03 22.77,8.03 23.02,7.78 23.02,7.37 22.82,7.17 15.7,7.17 11.67,11.21 11.67,12.35 8.77,15.25 8.77,16.16
VCC2V8_DVP on TOP: 12.28,11.49 11.67,11.49 11.59,11.41 11.59,8.54 11.82,8.31 13.42,8.31 13.6,8.49 13.6,10.37 13.49,10.47 12.66,10.47 12.4,10.73 12.4,11.36
VCC2V8_DVP1 on TOP: 24.06,6.05 24.06,7.22 24.75,7.91 25.53,7.91 25.61,7.98 25.62,7.98 25.79,8.09 25.9,8.26 25.9,8.27 25.94,8.31 25.94,8.67 25.76,8.85 25.76,9.41 25.79,9.43 27.64,9.43 27.85,9.63 27.85,12.43 27.92,12.5 28.56,12.5 28.68,12.38 28.68,11.01 28.96,10.73 29.85,10.73 29.98,10.6 29.98,9.56 29.23,8.81 28.49,8.81 25.79,6.1 25.26,6.1 25.1,5.95 24.16,5.95
VCC2V8_DVP2 on TOP: 36.08,10.68 35.26,10.68 35.21,10.62 35.21,9.43 34.98,9.2 34.98,7.65 35.06,7.58 36,7.58 36.02,7.55 36.02,6.05 36.05,6.03 36.33,6.03 36.35,6.05 36.35,7.65 37.35,8.64 37.35,9.51 37.19,9.66 36.3,9.66 36.11,9.85 36.11,10.64
VCC3V3_E on TOP: 101.23,27.85 101.1,27.72 97.31,27.72 97.19,27.85 97.19,28.96 97.26,29.04 97.59,29.04 97.77,29.22 97.77,29.8 98.28,30.31 99.88,30.31 99.98,30.41 103.59,30.41 103.82,30.18 103.82,29.42 103.72,29.32 103.67,29.32 103.67,29.34 101.63,29.34 101.23,28.94
VCC3V3_PHY0 on BOTTOM: 56.49,59.01 56.49,59.39 57.01,59.9 57.18,59.9 58.15,60.87 59.72,60.87 59.82,60.97 59.82,61.09 59.95,61.22 61.02,61.22 61.07,61.17 61.07,61.02 61.22,60.87 61.66,60.87 61.75,60.86 62.01,60.87 62.09,60.79 62.09,60.43 62.08,60.43 62.05,60.25 62.08,60.07 62.09,60.06 62.09,60 62.01,59.93 60.79,59.93 60.71,59.85 60.71,59.32 60.54,59.14 59.85,59.14 59.72,59.27 59.72,59.9 59.67,59.95 58.86,59.95 58.81,59.99 58.76,60.02 58.36,60.04 58.08,59.74 58.08,59.73 57.36,59.01 56.74,59.01
VCC3V3_PHY2 on BOTTOM: 77.53,58.83 77.45,58.92 77.44,58.92 76.63,58.92 76.56,58.99 76.56,59.29 77.88,60.61 77.88,61.96 78.7,62.77 79.15,62.77 79.4,62.52 79.4,62.39 79.4,62.35 79.41,62.3 79.41,61.88 79.61,61.68 79.61,60.61 79.56,60.56 79.43,60.56 78.39,59.52 78.39,58.88 78.34,58.83
VCC3V3_SD_OUT on TOP: 109.62,69.39 109.38,69.63 109.38,70.48 109.4,70.48 109.4,71.69 109.38,71.69 109.38,71.79 109.35,71.81 108.34,71.81 107.86,72.3 107.12,72.3 106.94,72.47 106.94,73.64 106.66,73.92 106.66,74.62 106.67,74.67 106.67,74.73 106.67,76.33 106.67,76.38 106.66,76.51 106.99,76.84 107.5,76.84 107.73,76.61 107.73,74.45 108.49,73.69 109.68,73.69 109.72,73.65 109.76,73.65 110.6,72.82 110.6,72.42 110.59,72.42 110.59,71.17 110.51,70.94 110.56,70.69 110.6,70.62 110.6,70.59 110.78,70.42 110.78,69.5 110.66,69.39
VCC3V3_SD_OUT on TOP: 101.12,55.35 100.9,55.58 100.9,56.19 101.01,56.31 102.28,56.31 102.47,56.12 102.47,55.7 102.3,55.52 102.3,55.46 102.19,55.35
VCC3V3_SD_OUT on TOP: 91.47,31.78 91.36,31.78 89.31,33.83 89.31,34.07 89.69,34.45 90.2,34.45 91.98,32.67 91.98,32.29
VCC3V3_SD_OUT on BOTTOM: 102.27,31.4 102.16,31.45 102.04,31.47 102.02,31.47 101.84,31.66 101.84,32.39 102.06,32.62 102.6,32.62 103.79,33.81 103.79,34.96 103.28,35.47 103.28,42.7 102.9,43.09 102.9,49.41 103.23,49.74 103.87,49.74 104.02,49.59 104.02,49.56 104.05,49.56 104.17,49.44 104.17,43.85 104.55,43.47 104.55,36.48 105.27,35.77 105.27,33.08 103.59,31.4
VCC3V3_SD_OUT on BOTTOM: 88.22,31.66 87.41,32.46 87.41,33.05 88.55,34.2 90.46,34.2 91.09,33.56 91.09,33.05 90.2,32.16 89.19,32.16 88.68,31.66
VCC3V3_SD_OUT on BOTTOM: 101.1,55.53 100.9,55.74 100.9,57.46 104.43,60.99 104.43,63.28 109.25,68.1 109.25,69.88 109.51,70.14 110.4,70.14 110.52,70.01 110.52,67.72 105.7,62.9 105.7,60.61 102.47,57.39 102.47,55.74 102.27,55.53
VCC3V3_SPK on TOP: 101.35,17.1 94.85,17.1 92.23,19.72 90.2,19.72 90.09,19.83 90.09,21.03 90.71,21.65 92.79,21.65 92.84,21.6 92.84,20.94 95.36,18.42 97.92,18.42 98.28,18.07 99.09,18.07 99.35,18.07 100.11,18.07 101.48,18.07 101.58,17.97 101.58,17.33
VCC3V3_SYS on TOP: 15.18,32.98 15.18,32.99 13.96,32.99 13.95,33 13.95,33.61 14.08,33.74 15.37,33.74 15.58,33.94 15.58,34.86 15.65,34.93 16.29,34.93 17.1,34.12 17.1,33.43 16.87,33.21 15.5,33.21 15.27,32.98
VCC3V3_SYS on TOP: 44.99,24.8 44.88,24.91 44.86,24.91 42.97,26.81 42.97,32.51 43.77,33.31 44.91,33.31 45.32,32.9 45.32,27.29 45.37,27.24 45.37,27.21 61.12,27.21 61.42,27.52 61.42,36.2 61.86,36.63 63.13,36.63 63.53,36.23 63.53,26.32 62.01,24.8
VCC3V3_SYS on TOP: 27.72,28.48 27.59,28.61 27.59,31.4 27.82,31.63 28.66,31.63 29.34,32.31 29.34,32.39 29.5,32.54 29.5,33.31 29.86,33.67 29.91,33.67 29.91,33.72 30,33.81 30,35.97 30.26,36.23 30.51,36.23 30.77,36.48 30.77,39.28 30.89,39.4 32.16,39.4 32.42,39.15 32.42,33.43 32.42,31.78 32.04,31.4 30.96,31.4 29.27,29.71 29.27,28.66 29.09,28.48
VCC3V3_SYS on TOP: 105.93,32.32 103.65,34.59 91.89,34.59 91.6,34.88 91.6,36.25 91.82,36.47 95.93,36.47 95.97,36.43 104.12,36.43 104.13,36.44 106.29,36.44 108.74,33.99 110.73,33.99 111.08,33.64 111.08,32.54 110.85,32.32
VCC3V3_SYS on BOTTOM: 24.54,30.13 23.55,31.12 22.16,31.12 21.47,31.81 17.79,31.81 16.39,33.21 16.39,33.92 16.8,34.32 22.18,34.32 24.04,32.47 24.37,32.47 25.18,31.66 27,31.66 27.23,31.43 27.31,31.43 27.34,31.4 29.24,31.4 29.5,31.15 29.5,30.35 29.28,30.13 27.26,30.13 26.9,30.39 26.49,30.25 26.08,30.39 25.73,30.13
VCC3V3_SYS on BOTTOM: 107.86,32.8 107.22,33.43 107.22,34.32 107.6,34.7 112.17,34.7 113.32,35.85 120.05,35.85 120.34,35.56 120.34,35.54 120.47,35.3 120.72,35.17 120.73,35.16 121.32,34.58 121.32,34.32 120.94,33.94 119.29,33.94 118.65,34.58 114.71,34.58 113.28,33.14 112.94,33.08 112.73,32.8
VCC3V3_SYS on BOTTOM: 43.5,30.89 37.72,36.68 34,36.68 33.43,37.24 33.36,37.24 33.35,37.25 33.12,37.35 32.87,37.32 32.8,37.29 32.74,37.24 31.27,37.24 30.89,37.62 30.89,39.53 31.08,39.72 35.14,39.72 35.15,39.68 35.18,39.58 35.24,39.49 35.64,39.3 36.03,39.53 38.46,39.53 42.32,35.67 42.32,35.15 42.28,35.11 42.29,35.1 42.6,34.71 43.09,34.81 43.11,34.83 44.41,34.83 45.27,33.97 45.27,31.22 44.94,30.89
VCC3V3_SYS on BOTTOM: 84.82,34.45 82.39,36.88 75.06,36.88 75.06,36.87 75.03,36.87 74.81,36.85 74.63,36.74 70.39,36.74 67.6,33.94 65.56,33.94 65.54,33.97 61.93,33.97 61.42,34.48 61.42,36.38 61.75,36.71 66.94,36.71 69.17,38.95 83.25,38.95 85.29,36.9 85.45,36.78 85.65,36.71 85.66,36.71 85.76,36.61 87.84,36.61 88.19,36.47 88.53,36.62 88.84,36.5 89.16,36.61 90.93,36.61 91.27,36.47 91.61,36.61 92.87,36.61 93.25,36.23 93.25,34.45 92.87,34.07 90.96,34.07 90.58,34.45 89.57,34.45
VCC5V0_HUB2 on TOP: 101.38,72.3 101.33,72.35 101.33,72.55 101.25,72.63 101.25,72.68 100.87,73.06 99.98,73.06 99.98,74.71 100.62,75.34 100.62,78.26 99.98,78.9 98.08,78.9 97.19,78.01 94.38,78.01 94.37,78.02 93.6,78.22 92.82,78.02 92.81,78.01 92.74,78.01 92.55,77.83 92.47,77.76 91.15,76.44 90.41,76.44 89.97,76.87 89.97,77.43 90.56,78.01 91.27,78.01 91.88,78.62 91.88,80.3 92.26,80.68 102.01,80.68 103.41,79.28 103.41,76.54 103.38,76.44 103.37,76.33 103.37,74.73 103.38,74.61 103.41,74.51 103.41,72.55 103.16,72.3
VCC5V0_HUB3 on TOP: 130.82,60.21 129.4,61.63 127.87,61.63 127.52,61.27 127.52,61.09 127.39,60.97 126.8,60.97 126.73,61.04 126.73,63.15 126.91,63.33 128.04,63.33 128.04,63.33 129.07,63.33 129.07,63.33 130.92,63.33 131.63,62.62 132.47,62.62 132.64,62.45 132.64,60.32 132.52,60.21
VCC5V0_HUB4 on TOP: 131.24,48.69 129.08,50.84 129.08,50.86 129.06,50.86 129.01,50.91 127.82,50.91 127.57,50.66 127.57,50.38 127.44,50.25 126.83,50.25 126.73,50.35 126.73,52.43 126.91,52.61 130.21,52.61 131.73,51.09 132.52,51.09 132.64,50.97 132.64,50.72 132.62,50.72 132.62,48.84 132.47,48.69
VCC5V_SYS on TOP: 104.22,71.66 103.94,71.94 103.94,73.62 104.27,73.95 106.23,73.95 106.69,73.49 106.69,71.81 106.54,71.66
VCC5V_SYS on TOP: 23.02,36.35 23.02,37.5 23.15,37.62 23.15,39.66 23.53,40.04 23.53,42.07 23.4,42.2 21.24,42.2 20.99,42.45 20.99,44.76 21.22,44.99 22.21,44.99 22.51,44.69 22.51,43.97 25.43,43.97 26.78,45.32 26.78,47.23 27.01,47.45 27.01,51.47 28.15,52.61 30.39,52.61 30.51,52.48 30.51,51.72 30.77,51.47 31.12,51.47 31.12,45.35 29.24,43.47 29.24,41.97 26.32,39.05 26.32,37.24 25.43,36.35
VCC5V_SYS on TOP: 102.37,21.19 99.17,21.19 98.89,21.47 98.89,23.07 99.3,23.48 101.35,23.48 101.58,23.71 101.58,23.91 101.76,24.08 101.76,24.24 101.79,24.26 102.52,24.26 102.75,24.04 102.75,21.57
VCC5V_SYS on TOP: 126.27,47.86 126.27,48.6 126.6,48.93 127.44,48.93 127.67,48.7 127.67,48.19 127.87,47.99 128.73,47.99 128.91,47.81 128.91,45.85 126.56,43.51 125.75,43.51 125.18,42.93 124.39,42.93 123.98,42.53 123.98,38.84 125.51,37.32 125.51,34.83 125.25,34.58 123.6,34.58 121.44,36.74 121.44,44.03 122.73,45.31 123.9,45.31 124.39,45.8 124.39,46.31 124.82,46.74 125.66,46.74 125.66,47.33 125.71,47.38 125.79,47.38
VCC5V_SYS on TOP: 87.26,53.32 87.03,53.55 87.03,56.93 87.15,57.06 88.96,57.06 89.16,56.85 89.16,55.89 89.06,55.79 89.06,54.57 89.44,54.19 89.44,53.55 89.21,53.32
VCC5V_SYS on TOP: 98.38,70.06 97.26,70.06 97.16,70.16 97.16,71.64 97.67,72.14 99.35,72.14 99.69,71.8 99.69,70.48 99.47,70.26 98.58,70.26
VCC5V_SYS on TOP: 126.96,56.37 126.58,56.76 126.58,57.11 126.78,59.52 126.88,59.62 127.36,59.62 127.69,59.29 127.69,59.06 128.07,58.68 128.96,58.68 129.17,58.48 129.17,57.08 128.94,56.85 128,56.85 127.52,56.37
VCC5V_SYS on TOP: 87.36,24.8 87.36,25.53 87.49,25.66 88.12,25.66 88.17,25.71 88.17,26.09 88.37,26.3 90.36,26.3 90.58,26.07 90.58,24.04 88.12,24.04
VCC5V_SYS on TOP: 74.79,30.51 74.79,31.43 74.71,31.51 74.71,33.54 74.94,33.76 74.94,34.91 75.34,35.31 75.34,35.31 75.57,35.55 75.57,42.55 75.64,42.62 75.67,42.61 76.12,42.68 76.3,43.1 76.33,43.18 76.41,43.21 80.8,43.21 81.31,42.7 81.31,42.4 81.31,42.39 81.27,42.19 81.31,41.98 81.31,41.97 81.31,41.4 81.31,41.39 81.27,41.19 81.31,40.98 81.31,40.97 81.31,40.4 81.31,40.39 81.27,40.19 81.31,39.98 81.31,39.97 81.31,39.4 81.31,39.39 81.27,39.19 81.31,38.98 81.31,38.97 81.31,38.4 81.31,38.39 81.27,38.19 81.31,37.98 81.31,37.97 81.31,37.4 81.31,37.39 81.27,37.19 81.31,36.98 81.31,36.97 81.31,36.4 81.31,36.39 81.27,36.19 81.31,35.98 81.31,35.97 81.31,35.4 81.31,35.39 81.27,35.19 81.31,34.98 81.31,34.97 81.31,34.4 81.31,34.39 81.27,34.19 81.31,33.98 81.31,33.97 81.31,33.4 81.29,33.35 81.27,33.25 81.27,33.16 81.27,33.13 81.01,32.88 81.01,30.64 80.63,30.26 75.04,30.26
VCC5V_SYS on BOTTOM: 85.29,44.84 85.25,44.56 85.38,44.31 85.38,44.1 82.82,41.55 79.26,41.55 78.99,41.81 78.99,41.83 78.92,42.01 78.77,42.15 78.77,43.49 79.22,43.94 79.33,43.97 79.39,43.89 80.12,43.49 80.35,44.28 80.32,44.31 83.03,47.02 83.03,49.69 86.46,53.11 86.46,56.92 86.59,57.06 88.55,57.06 88.89,56.72 88.89,52.49 85.29,48.89 85.29,44.85
VCC5V_SYS on BOTTOM: outline of 119 points within 23.02,18.35 127.13,38.8
VCC5V_SYS on BOTTOM: 117.38,74.96 121.32,74.96 129.95,66.33 129.95,47.28 129.06,46.39 126.4,46.39 124.72,48.07 124.72,48.83 124.62,48.92 124.62,58.83 123.86,59.6 123.86,59.74 123.94,59.74 123.95,59.71 124.39,59.5 124.79,59.78 124.73,60.26 124.28,60.45 124.26,60.45 123.86,60.85 123.86,62.39 123.67,62.58 123.67,62.67 122.18,64.16 122.18,64.19 122.14,64.45 121.97,64.65 121.77,64.73 121.54,64.7 121.19,65.06 120.3,65.06 114.78,70.58 112.36,70.58 111.67,71.28 111.28,71.28 110.99,71.38 110.7,71.28 110.14,71.28 107.2,68.33 98.97,68.33 98.58,68.71 98.58,69.76 98.33,70.01 97.44,70.01 97.06,70.39 97.06,73.06 98.46,74.45 106.08,74.45 107.47,75.85 111.54,75.85 112.17,76.49 115.86,76.49
VCC_1V8_OUT on TOP: 36.3,46.24 35.68,45.61 34.82,45.61 34.68,45.75 34.68,46.36 34.7,46.39 34.7,46.79 35.06,47.15 35.95,47.15 36.3,46.79
VCC_1V8_OUT on TOP: 35.14,41.33 35.29,41.18 35.29,40.57 34.98,40.27 34.02,40.27 33.74,40.55 33.74,41.08 33.99,41.33
VCC_1V8_OUT on TOP: 7.37,62.97 5.95,62.97 5.9,63.02 5.9,63.69 5.98,63.76 7.4,63.76 7.4,63.76 8.54,63.76 8.8,63.51 8.8,63.3 8.61,63.11 7.51,63.11
VCC_1V8_OUT on TOP: 63.02,38.13 63.02,37.14 62.82,36.94 61.53,36.94 61.37,37.09 61.37,39.15 60.1,40.42 46.01,40.42 44.99,41.43 44.99,41.79 45.3,42.1 45.83,42.1 46.43,41.5 60.68,41.5 62.52,39.66 62.52,38.64
VCC_1V8_OUT on BOTTOM: 85.63,36.86 83.29,39.2 69.07,39.2 66.81,36.94 61.5,36.94 61.37,37.07 61.37,38.29 61.53,38.44 65.77,38.44 67.93,40.6 76.89,40.6 77.1,40.39 83.6,40.39 86.24,37.75 87.03,37.75 87.15,37.62 87.15,36.99 87.03,36.86
VCC_1V8_OUT on BOTTOM: 10.83,60.61 9.94,61.5 9.94,62.06 9.97,62.12 9.88,62.7 9.29,62.74 9.19,62.66 9.12,62.55 9.11,62.52 6.38,62.52 6,62.14 5.49,62.14 5.37,62.26 5.37,63.41 5.72,63.76 8.54,63.76 9.84,65.06 14.89,65.06 15.65,64.29 15.65,61.12 15.15,60.61 14.29,60.61 13.62,60.91 12.95,60.61 12.29,60.61 11.78,60.9 11.19,60.8 11.07,60.72 10.96,60.63 10.95,60.61
VCC_1V8_OUT on BOTTOM: 46.01,42.27 46.95,41.33 46.95,40.88 46.36,40.29 45.96,40.29 44.99,41.26 44.99,41.84 45.42,42.27
VCC_3V3 on TOP: 31.02,20.1 30.89,20.23 30.89,21.37 30.89,21.37 30.89,21.44 30.82,21.44 30.77,21.5 29.75,21.5 28.73,22.51 27.85,22.51 27.59,22.77 27.59,25.81 27.56,25.84 27.56,25.89 27.51,25.89 27.34,26.07 26.45,26.07 26.19,26.32 26.19,27.59 26.45,27.85 29.24,27.85 29.5,27.59 29.5,25.05 31.24,23.31 31.24,23.3 31.25,23.3 31.27,23.27 33.31,23.27 33.56,23.02 33.56,21.11 33.43,20.99 32.16,20.99 32.04,20.86 32.04,20.23 31.91,20.1
VCC_3V3 on TOP: 5.95,64.02 5.87,64.09 5.87,64.7 7.3,64.7 7.36,64.76 7.41,64.76 7.5,64.85 7.5,64.9 7.53,64.93 7.53,66.38 7.65,66.5 8.85,66.5 9.05,66.3 9.05,64.29 8.77,64.02
VCC_3V3 on TOP: 35.21,13.88 35.21,12.22 35.26,12.17 35.77,12.17 35.9,12.3 35.9,12.45 36.33,12.89 37.37,12.89 37.47,12.99 37.47,13.9 37.32,14.05 35.39,14.05
VCC_3V3 on TOP: 105.57,6.44 105.39,6.26 103.64,6.26 103.51,6.38 103.51,7.02 103.61,7.12 103.92,7.12 104.76,7.96 105.49,7.96 105.57,7.88
VCC_3V3 on TOP: 54.42,11.39 54.39,11.42 54.39,13.09 54.59,13.29 56.5,13.29 56.7,13.09 56.7,11.51 56.57,11.39
VCC_3V3 on TOP: 73.06,9.81 72.93,9.94 72.93,10.83 73.18,11.08 74.2,11.08 74.45,10.83 74.45,4.94 73.36,3.84 72.3,3.84 72.04,4.1 72.04,5.62 73.06,6.64
VCC_3V3 on TOP: 18.96,13.34 18.96,15.37 19.06,15.48 19.18,15.48 19.97,16.26 21.06,16.26 21.22,16.11 21.22,14.74 21.06,14.59 20.2,14.59 19.92,14.31 19.92,13.39 19.79,13.27 19.03,13.27
